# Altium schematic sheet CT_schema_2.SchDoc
size 383 x 218 mm
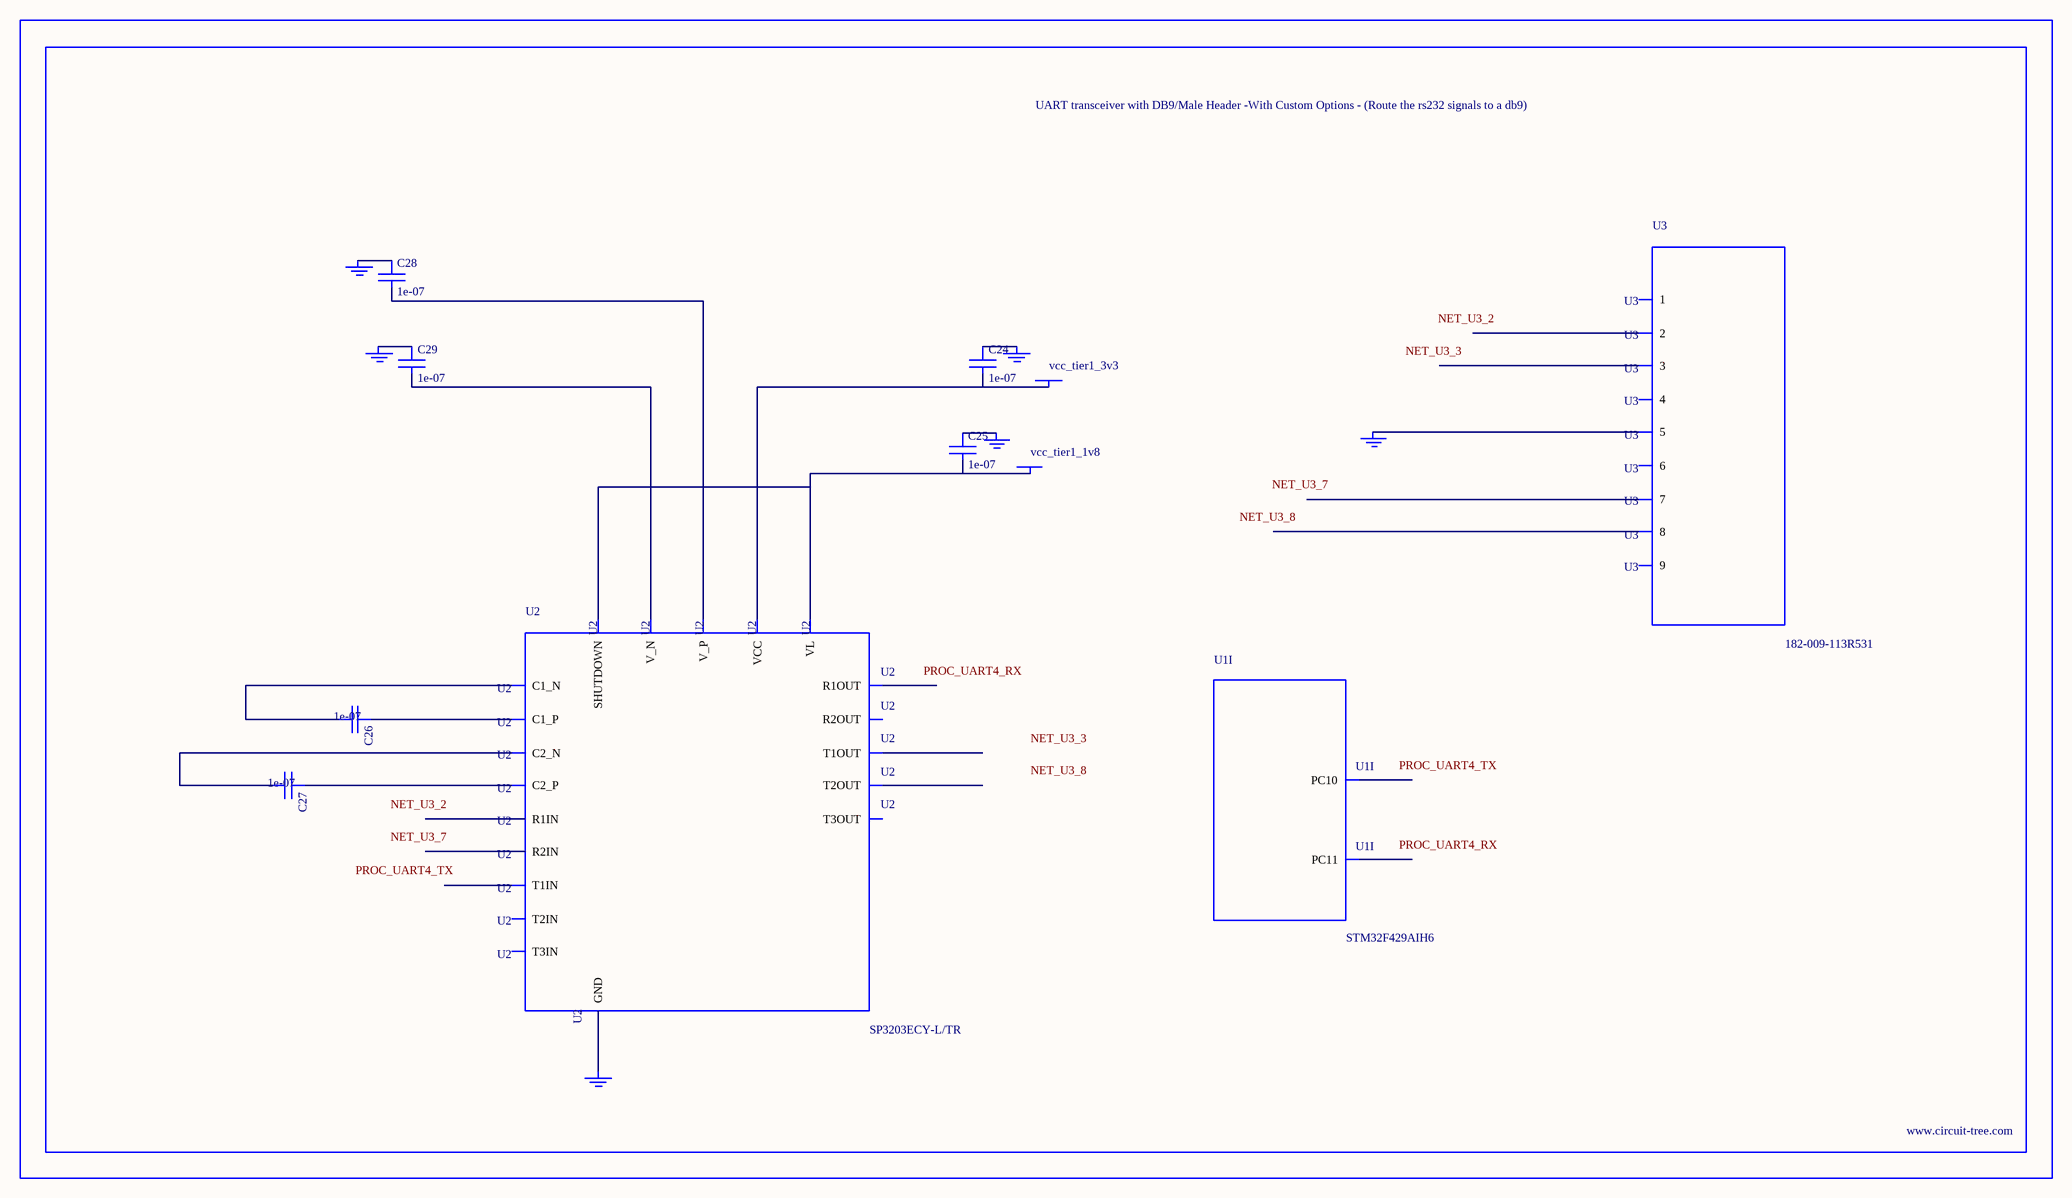
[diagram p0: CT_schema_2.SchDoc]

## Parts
BORDER1  (no value)
C24  1e-07  [C0402]
C25  1e-07  [C0402]
C26  1e-07  [C0402]
C27  1e-07  [C0402]
C28  1e-07  [C0402]
C29  1e-07  [C0402]
GND_INSTANCE_1_0  (no value)
GND_INSTANCE_1_1  (no value)
GND_INSTANCE_1_2  (no value)
GND_INSTANCE_1_3  (no value)
GND_INSTANCE_1_4  (no value)
GND_INSTANCE_1_5  (no value)
POWER_INSTANCE_1_0  vcc_tier1_1v8
POWER_INSTANCE_1_1  vcc_tier1_3v3
U1  STM32F429AIH6  [UFBGA169]  (part I of 12)
U2  SP3203ECY-L/TR  [TSSOP20-I]
U3  182-009-113R531  [182-009-MALE]

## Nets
NetC24_1: C24.1 GND_INSTANCE_1_3.0(GND)
NetC24_2: C24.2 POWER_INSTANCE_1_1.0(PWR) U2.19(VCC)
NetC25_1: C25.1 GND_INSTANCE_1_2.0(GND)
NetC25_2: C25.2 POWER_INSTANCE_1_0.0(PWR) U2.12(VL) U2.20(SHUTDOWN)
NetC26_1: C26.1 U2.1(C1_P)
NetC26_2: C26.2 U2.3(C1_N)
NetC27_1: C27.1 U2.4(C2_P)
NetC27_2: C27.2 U2.5(C2_N)
NetC28_1: C28.1 GND_INSTANCE_1_0.0(GND)
NetC28_2: C28.2 U2.2(V_P)
NetC29_1: C29.1 GND_INSTANCE_1_1.0(GND)
NetC29_2: C29.2 U2.6(V_N)
NetGND_INSTANCE_1_4_0: GND_INSTANCE_1_4.0(GND) U2.18(GND)
NetGND_INSTANCE_1_5_0: GND_INSTANCE_1_5.0(GND) U3.5

Not connected (* = marked no-connect by the designer): U1 B10(PC11) C10(PC10); U2 7(T1IN) 8(T2IN) 9(T3IN) 10(R2OUT) 11(R1OUT) 13(R2IN) 14(R1IN) 15(T3OUT) 16(T2OUT) 17(T1OUT); U3 1 2 3 4 6 7 8 9

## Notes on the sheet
- Labels drawn without touching a wire or pin: NET_U3_2, NET_U3_3, NET_U3_7, NET_U3_8, PROC_UART4_RX, PROC_UART4_TX

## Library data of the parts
BORDER1 = BORDER_PAGE1
C24-C29 = C0402C104K3RACTU
GND_INSTANCE_1_0-GND_INSTANCE_1_5 = GND
POWER_INSTANCE_1_0 POWER_INSTANCE_1_1 = PWR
